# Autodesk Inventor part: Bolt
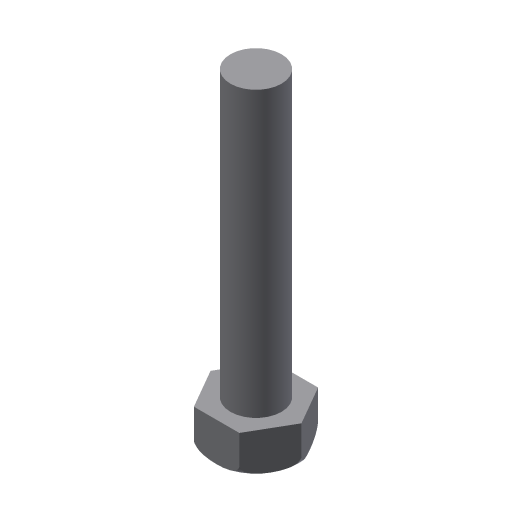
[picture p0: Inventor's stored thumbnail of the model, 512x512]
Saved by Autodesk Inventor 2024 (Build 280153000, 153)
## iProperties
Shininess: 77.0
Length Units: 11269
Angle Units: 11279
Time Units: 11290
Mass Units: 11283
Length Display Precision: 3
Angle Display Precision: 2
Created: 2002-02
Part Number: Bolt
Document SubType Name: Modeling
Designer: ***
Density: 1 g/cm^3
Material: Generic
Appearance: Default
Density: 0.0
Volumn: 0.0
Area: 0.0
PropertySet Name: Model Information
Control State: 0
Master: False
Checked Out: False
Author: ***
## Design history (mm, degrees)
sketch "Sketch1"
  geometry: C1 r 4 at (0, 0)
  constraints: 1 centre point
  dimensions: "d0" = 8 diameter of C1
extrude "Extrusion1" new body sketch "Sketch1" stored distance "d1" = 3.5; taper "d2" = 0 deg
fillet "Fillet1" dims "d3" = 1
sketch "Sketch2"
  geometry: L1 (4, 0)-(2, -3.464); L2 (2, -3.464)-(-2, -3.464); L3 (-2, -3.464)-(-4, 0); L4 (-4, 0)-(-2, 3.464); L5 (-2, 3.464)-(2, 3.464); L6 (2, 3.464)-(4, 0); 2 further points
  constraints: 12 end point, 1 coincident, 11 other
extrude "Extrusion2" sketch "Sketch2" extent not by distance; stored distance "d4" = 3.5; taper "d5" = 0 deg
sketch "Sketch3"
  geometry: C1 r 2.25 at (0, 0)
  constraints: 1 centre point
  dimensions: "d6" = 4.5 diameter of C1
extrude "Extrusion3" join sketch "Sketch3" distance "d7" = 25; taper "d8" = 0 deg
body "Solid1"
